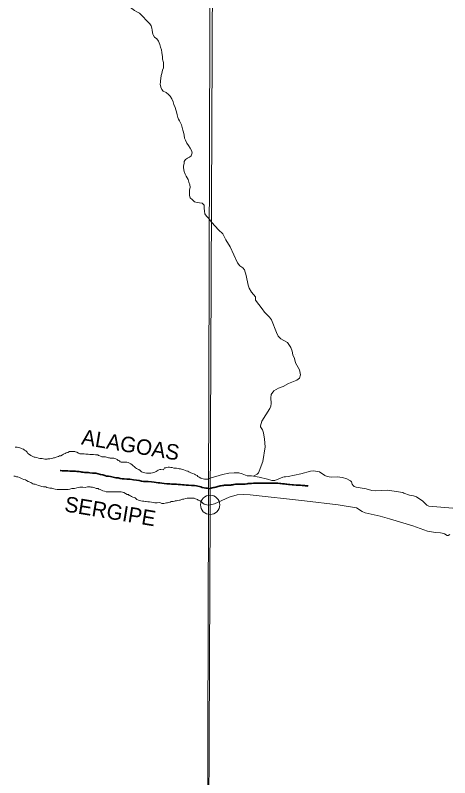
# Model space of a CAD drawing. Extents: x 553962 to 842807, y 8883888 to 9032388.
# Drawn here: x 595557 to 597811, y 8902976 to 8906931 of the extents above; entities that cross this region are included whole.
import ezdxf
from ezdxf.enums import TextEntityAlignment as Align

# ---------------------------------------------------------------- set-up
doc = ezdxf.new("R2010")
doc.units = 0
doc.header["$LTSCALE"] = 200
doc.header["$PDMODE"] = 32
doc.header["$PDSIZE"] = 100
doc.linetypes.add('LONG_DASH_SHORT_DASH', pattern=[9.9, 6, -1.2, 1.5, -1.2])
doc.layers.add('6', color=7, linetype='Continuous', lineweight=13)

msp = doc.modelspace()

# ---------------------------------------------------------------- linework, layer by layer
at = {"layer": '6'}
msp.add_line((597009.3, 8905170.6), (597009.5, 8905170.5), dxfattribs=at)
for points in [[(596655.5, 8924715.8), (596593.3, 8909930.3), (596531.7, 8896026.7)], [(596271.3, 8906832.7), (596268.8, 8906840.6), (596267.4, 8906852.6), (596266, 8906863.6), (596262.5, 8906875.6), (596254.5, 8906886.2), (596246.1, 8906895.2), (596235.1, 8906906.3), (596222.2, 8906920.4), (596211.2, 8906932.4), (596201.2, 8906941), (596187.3, 8906949.1), (596175.3, 8906955.7), (596161.8, 8906966.2), (596149.8, 8906973.8), (596139.9, 8906984.4), (596128.4, 8906996.9), (596121.5, 8907010), (596118, 8907020.5), (596117.5, 8907024.2)], [(596279.7, 8906817), (596272.3, 8906829.5), (596271.3, 8906832.7)], [(596461.2, 8906005.4), (596461.2, 8906022.7), (596463.8, 8906039.2), (596463.4, 8906051.2), (596457.4, 8906065.3), (596453.5, 8906078.3), (596444.6, 8906095.4), (596439.1, 8906106.9), (596433.7, 8906120.9), (596429.8, 8906138.5), (596429.8, 8906149), (596432.9, 8906162), (596433.9, 8906171.5), (596439.5, 8906182), (596451, 8906189.9), (596461, 8906195.4), (596470.1, 8906202.3), (596474.2, 8906216.8), (596471.2, 8906229.4), (596464.2, 8906241.4), (596455.8, 8906256), (596447.9, 8906268), (596439.9, 8906282.6), (596434.5, 8906292.6), (596433, 8906308.7), (596429.1, 8906323.7), (596426.2, 8906335.2), (596422.7, 8906348.8), (596419.3, 8906361.8), (596413.8, 8906373.3), (596408.8, 8906382.4), (596403.4, 8906390.9), (596399.9, 8906400.4), (596397, 8906413.4), (596393.6, 8906429), (596389.6, 8906440), (596386.2, 8906452.6), (596379.7, 8906468.6), (596376.3, 8906481.6), (596368.8, 8906497.2), (596361.4, 8906511.2), (596351.4, 8906519.3), (596340, 8906529.4), (596324, 8906537.5), (596317.3, 8906546.3), (596312.9, 8906557.6), (596309.7, 8906572.8), (596311, 8906582.9), (596310.7, 8906590.6), (596312.8, 8906603.1), (596313.4, 8906618.6), (596316.9, 8906629.1), (596321.5, 8906645.1), (596325.6, 8906657.6), (596326.1, 8906673.6), (596325.7, 8906686.1), (596321.8, 8906703.6), (596321.3, 8906715.7), (596317.4, 8906737.2), (596316.5, 8906750.7), (596310, 8906765.8), (596307.1, 8906779.8), (596300.2, 8906796.3), (596291.2, 8906807.9), (596279.7, 8906817)], [(596838.8, 8905408.9), (596804, 8905452.2), (596802.6, 8905456.8), (596803.3, 8905469.9), (596782.8, 8905493.9), (596770.6, 8905515.5), (596764.7, 8905530.2), (596754.3, 8905581.4), (596745.9, 8905609.6), (596737.4, 8905621.2), (596722.8, 8905631.7), (596710.6, 8905646), (596672.1, 8905729.1), (596650.2, 8905765.8), (596633.6, 8905797.4), (596611.2, 8905818.6), (596577.4, 8905855.5), (596559.7, 8905877.5), (596548.7, 8905888.6), (596540.2, 8905900.2), (596538.3, 8905914.2), (596537.9, 8905930.7), (596537.5, 8905945.2), (596527, 8905955.3), (596513.5, 8905957.9), (596500.5, 8905959.4), (596487, 8905962.5), (596476, 8905972.6), (596464.6, 8905983.1), (596461.1, 8905995.7), (596461.2, 8906005.4)], [(596792.7, 8904540.1), (596811.4, 8904551.1), (596818.4, 8904557.4), (596822.7, 8904565.5), (596841.5, 8904615.9), (596853.2, 8904691.8), (596850.7, 8904732.7), (596845.1, 8904764.5), (596839.3, 8904781), (596829.4, 8904796.5), (596828.9, 8904802.2), (596837.1, 8904824.7), (596877.1, 8904890.7), (596882.8, 8904903.4), (596885.5, 8904918), (596882.5, 8904946.3), (596884.2, 8904964.5), (596897.9, 8904982), (596922.6, 8904996.6), (596946.5, 8905006.2), (596975.3, 8905021.5), (597017.5, 8905037.8), (597031.8, 8905049.4), (597037, 8905065), (597032.3, 8905091.9), (597011.4, 8905127.4), (597004.9, 8905150.7), (596996.7, 8905170.4), (596994.1, 8905188.6), (596987.3, 8905208), (596969.8, 8905234), (596935.4, 8905253.2), (596921.5, 8905266.1), (596912.2, 8905285.1), (596886, 8905350.5), (596875.4, 8905364.7), (596850.4, 8905390), (596838.8, 8905408.9)], [(595556.5, 8904690.4), (595567.5, 8904689.9), (595575, 8904688.3), (595585.5, 8904685.2), (595593, 8904682.7), (595599.9, 8904679.7), (595605.9, 8904675.6), (595612.4, 8904672.1), (595619.8, 8904665.5), (595623.3, 8904658), (595631.8, 8904653.4), (595637.2, 8904647.4), (595645.7, 8904643.3), (595654.7, 8904639.7), (595659.7, 8904638.2), (595669.6, 8904637.1), (595677.6, 8904633.6), (595684.1, 8904631.5)], [(595684.1, 8904631.5), (595696.6, 8904631.9), (595710.6, 8904628.3), (595718.1, 8904629.3), (595722.1, 8904629.3), (595726.6, 8904629.7), (595733.1, 8904629.7), (595737.1, 8904630.2), (595744.1, 8904632.1), (595751.7, 8904633.1), (595756.2, 8904634.6), (595760.7, 8904636), (595765.2, 8904637), (595769.2, 8904639), (595774.7, 8904640.4), (595781.2, 8904642.4), (595786.8, 8904645.4), (595793.3, 8904646.3), (595802.8, 8904650.3), (595807.8, 8904653.7), (595816.9, 8904657.2), (595821.4, 8904660.7), (595830.4, 8904663.6), (595839, 8904668.1), (595845, 8904668), (595850, 8904668), (595858, 8904667.9), (595866, 8904667.4), (595870.5, 8904665.8), (595877.5, 8904664.8), (595884.9, 8904659.7), (595891.4, 8904656.2), (595899.4, 8904656.1), (595903.4, 8904656.1), (595910.9, 8904656.1), (595914.9, 8904656), (595922.9, 8904655), (595927.4, 8904654.4), (595934.9, 8904653.9), (595943.4, 8904652.3), (595951.4, 8904652.3), (595956.4, 8904652.3), (595963.4, 8904652.2), (595973.4, 8904651.6), (595980.4, 8904651.1), (595984.9, 8904650.6), (595989.4, 8904647.5), (595995.3, 8904646), (596002.3, 8904641.9), (596006.8, 8904639.9), (596012.8, 8904639.9), (596025.8, 8904639.8), (596041.3, 8904635.2), (596045.8, 8904634.6), (596050.3, 8904633.6), (596056.3, 8904633.1), (596063.8, 8904633), (596067.8, 8904633), (596074.3, 8904632.4), (596079.3, 8904630.4), (596086.2, 8904626.9), (596090.2, 8904622.3), (596097.2, 8904619.3), (596100.7, 8904614.2), (596107.2, 8904613.2), (596113.7, 8904613.2), (596120.7, 8904613.1), (596124.7, 8904613.1), (596128.7, 8904613.1), (596136.2, 8904613), (596142.2, 8904611), (596149.6, 8904608.4), (596156.1, 8904604.4), (596163.6, 8904599.3), (596168, 8904593.3), (596174.5, 8904590.2), (596180.5, 8904583.7), (596186.9, 8904580.1), (596193.4, 8904576.1), (596197.9, 8904574.1), (596204.4, 8904570), (596211.3, 8904563.4), (596217.3, 8904560.4), (596222.8, 8904558.9), (596229.8, 8904557.3), (596238.8, 8904556.3), (596245.3, 8904556.2), (596249.3, 8904556.2), (596255.8, 8904556.1), (596260.3, 8904556.6), (596268.3, 8904557.6), (596272.8, 8904559), (596280.8, 8904561), (596288.9, 8904564.4), (596292.9, 8904567.9), (596298.4, 8904570.9), (596307, 8904574.3), (596312, 8904575.3), (596327, 8904573.2), (596331.5, 8904582.7), (596337.5, 8904584.1)], [(596337.5, 8904584.1), (596341.6, 8904585.6), (596350.1, 8904586.6), (596357.6, 8904586.5), (596364.6, 8904586), (596371.1, 8904585.9), (596379.5, 8904581.9), (596386.5, 8904581.3), (596393.5, 8904581.3), (596401.5, 8904580.7), (596408, 8904579.2), (596414, 8904578.1), (596419, 8904576.6), (596427, 8904575.5), (596432, 8904572.5), (596440, 8904569.4), (596444.5, 8904567.9), (596452, 8904566.9), (596457.4, 8904563.3), (596468.4, 8904558.2), (596478.9, 8904554.7), (596487.3, 8904550.1), (596492.3, 8904546.6), (596500.3, 8904543), (596504.3, 8904539), (596511.7, 8904535.4), (596519.2, 8904529.4), (596523.7, 8904527.8), (596531.7, 8904525.8), (596538.2, 8904524.7), (596545.2, 8904524.7), (596549.2, 8904524.7), (596554.2, 8904525.1), (596558.2, 8904525.1), (596568.1, 8904529.4), (596633, 8904549.7), (596665.5, 8904556.5), (596692.3, 8904558.4), (596717.2, 8904557), (596733.8, 8904552.4)], [(596822.7, 8904565.5), (596818.4, 8904557.4), (596811.4, 8904551.1), (596792.7, 8904540.1)], [(596823.3, 8904534.6), (596822.9, 8904534.3), (596866.1, 8904524.6), (596887.5, 8904518.1), (596904.4, 8904518.5), (596944.7, 8904535.2), (596952.2, 8904537.4), (596959.2, 8904537.7), (596972.2, 8904538.7), (597038.5, 8904552.3), (597088.9, 8904566.9), (597103.5, 8904567.8), (597135.1, 8904562.2), (597163.3, 8904544.4), (597175.5, 8904538.6), (597195.2, 8904535.8), (597227.3, 8904537.4), (597253.9, 8904534.1), (597277.1, 8904527.3), (597291.9, 8904517.4), (597296.9, 8904516.7), (597300.6, 8904511.3), (597305.1, 8904499.1), (597310, 8904491.8), (597315.9, 8904486.6), (597325.4, 8904483.2), (597377.2, 8904474.8), (597406.8, 8904466.6), (597425.4, 8904464.6), (597488, 8904467), (597567.9, 8904454.9)], [(596113, 8904457.9), (596106, 8904458.5), (596097.5, 8904459.1), (596092.5, 8904459.1), (596084.5, 8904459.1), (596079.5, 8904459.2), (596067.5, 8904459.2), (596057, 8904459.3), (596050, 8904459.4), (596042, 8904459.4), (596036.5, 8904459.5), (596028, 8904459.5), (596020, 8904462.6), (596012, 8904463.6), (596005, 8904467.7), (595998.5, 8904470.7), (595991.5, 8904472.8), (595987.1, 8904475.8), (595977.6, 8904476.9), (595969.6, 8904479.9), (595965.1, 8904481.5), (595958.6, 8904482.5), (595950.1, 8904484.1), (595945.1, 8904485.1), (595936.6, 8904485.2), (595932.1, 8904485.2), (595920.1, 8904482.3), (595908.6, 8904483.3), (595897.6, 8904483.4), (595892.1, 8904482.9), (595885.1, 8904482), (595877, 8904480.5), (595865, 8904477.1), (595851, 8904476.2), (595840.5, 8904473.3), (595832.5, 8904471.8), (595827, 8904470.9), (595816.4, 8904470.4), (595808.4, 8904470.5), (595798.4, 8904470.5), (595789.4, 8904470.6), (595783.9, 8904470.6), (595773.9, 8904470.7), (595763.9, 8904472.3), (595756.9, 8904473.8), (595747, 8904477.4), (595737, 8904478), (595730.5, 8904479.5), (595721, 8904481.1), (595715.5, 8904484.6), (595704.5, 8904485.7), (595695, 8904487.2), (595684.5, 8904490.3), (595678, 8904491.9), (595669.1, 8904494.9), (595661.1, 8904498), (595653.6, 8904499), (595649.1, 8904500.6), (595642.6, 8904503.6), (595637.6, 8904507.2), (595628.7, 8904510.2), (595623.7, 8904513.3), (595615.2, 8904518.3), (595609.7, 8904521.9), (595601.8, 8904522.9), (595593.3, 8904527), (595585.8, 8904529.5), (595579.3, 8904533.6), (595571.3, 8904536.1), (595563.8, 8904537.7), (595557.3, 8904539.7), (595550.4, 8904540.8)], [(596733.8, 8904552.4), (596760.4, 8904542.1), (596781.9, 8904541.7), (596822.9, 8904534.3)], [(596137.9, 8904445.3), (596128.4, 8904450.8), (596120.5, 8904454.9), (596113, 8904457.9)], [(596412.8, 8904415.9), (596408.8, 8904415.9), (596401.3, 8904414.5), (596394.3, 8904413), (596387.2, 8904411.6), (596383.2, 8904410.6), (596376.2, 8904409.6), (596366.7, 8904408.2), (596360.2, 8904405.2), (596351.2, 8904404.3), (596347.2, 8904402.8), (596341.2, 8904401.9), (596335.1, 8904399.9), (596328.6, 8904398.9), (596324.1, 8904398.5), (596317.1, 8904398.5), (596307.2, 8904403.6), (596293.1, 8904401.2), (596281.1, 8904402.3), (596273.1, 8904403.8), (596264.6, 8904405.4), (596253.7, 8904406.4), (596244.7, 8904407.5), (596236.7, 8904408.1), (596232.2, 8904409.1), (596224.2, 8904410.2), (596216.7, 8904411.2), (596208.7, 8904412.8), (596201.2, 8904414.3), (596196.2, 8904415.8), (596188.7, 8904418.9), (596184.2, 8904422.9), (596179.3, 8904428), (596173.3, 8904429), (596167.8, 8904432.1), (596160.3, 8904435.1), (596155.8, 8904438.6), (596148.8, 8904439.7), (596144.9, 8904444.7), (596137.9, 8904445.3)], [(597784.5, 8904240.9), (597780.8, 8904243.5), (597763, 8904246.9), (597737.7, 8904248), (597696.4, 8904255.7), (597619.9, 8904282.1), (597498.2, 8904319.6), (597450, 8904332.9), (597372.6, 8904350.3), (597356, 8904357.7), (597326.5, 8904376.3), (597232.9, 8904391.8), (597058.1, 8904411.6), (596775.1, 8904444.1), (596742.4, 8904446), (596707.5, 8904442.8), (596667.4, 8904431.6), (596590.1, 8904397.6), (596568.1, 8904391.5), (596558.7, 8904389.9), (596551.2, 8904391.5), (596544.2, 8904394), (596537.7, 8904395.6), (596530.7, 8904401.1), (596526.2, 8904404.6), (596520.3, 8904409.2), (596515.8, 8904412.2), (596506.8, 8904415.8), (596502.3, 8904419.3), (596492.4, 8904422.4), (596485.4, 8904425.4), (596475.9, 8904426), (596467.4, 8904426.1), (596458.4, 8904426.1), (596449.4, 8904426.2), (596440.4, 8904425.2), (596431.8, 8904421.3), (596424.8, 8904421.3), (596420.3, 8904419.9), (596412.8, 8904415.9)], [(597567.9, 8904454.9), (597572.2, 8904452.6), (597602.6, 8904441.6), (597622.9, 8904438.2), (597638, 8904432.9), (597672.2, 8904410.2), (597691.4, 8904390.6), (597701.7, 8904384.3), (597826.9, 8904374.3)], [(597812.2, 8904237.9), (597802.9, 8904232.5), (597797.6, 8904231.9), (597784.5, 8904240.9)]]:
    msp.add_lwpolyline(points, dxfattribs=at)
msp.add_lwpolyline([(596575.8, 8909932.4), (585614.8, 8909969.8), (585583.8, 8898914.4), (596544.8, 8898874.9)], close=True, dxfattribs=at)
at = {"layer": '6', "linetype": 'LONG_DASH_SHORT_DASH', "lineweight": 35}
for points in [[(596403.1, 8904497.6), (596393.1, 8904498.1), (596385.2, 8904498.7), (596380.2, 8904498.7), (596375.2, 8904499.2), (596367.2, 8904499.3), (596358.7, 8904499.8), (596344.2, 8904500.9), (596330.2, 8904502), (596318.2, 8904504.5), (596307.2, 8904505.1), (596298.2, 8904506.1), (596288.7, 8904507.2), (596278.2, 8904509.8), (596264.2, 8904510.3), (596247.2, 8904512.9), (596234.7, 8904513), (596223.2, 8904513.5), (596212.2, 8904514.6), (596200.3, 8904518.2), (596185.3, 8904519.2), (596169.8, 8904521.8), (596151.3, 8904524.9), (596136.3, 8904525), (596122.8, 8904526.1), (596111.8, 8904527.1), (596101.3, 8904528.2), (596090.4, 8904531.3), (596079.4, 8904531.8), (596065.9, 8904534.4), (596051.9, 8904538), (596040.4, 8904540.5), (596030.9, 8904541.1), (596021.4, 8904543.6), (596012, 8904546.7), (596000, 8904549.8), (595987, 8904552.8), (595974.5, 8904555.4), (595957.5, 8904556), (595944.5, 8904557.1), (595937.6, 8904559.6), (595929.5, 8904559.6), (595924, 8904559.7), (595915.6, 8904560.2), (595909.6, 8904560.7), (595903.1, 8904561.8), (595897.1, 8904562.3), (595889.1, 8904563.9), (595883.1, 8904564.4), (595877.1, 8904564.9), (595870.1, 8904566), (595860.6, 8904566), (595850.1, 8904566.6), (595840.6, 8904567.1), (595830.1, 8904567.2), (595819.1, 8904567.2), (595811.1, 8904567.8), (595805.6, 8904567.8), (595800.1, 8904568.8), (595791.6, 8904569.4), (595790.2, 8904569.7)], [(596573, 8904478.7), (596564, 8904475.2), (596553, 8904478.3), (596546, 8904478.8), (596537, 8904479.3), (596527, 8904481.9), (596519.6, 8904484.9), (596512.1, 8904486), (596504.6, 8904488.5), (596497.1, 8904489.6), (596487.6, 8904492.1), (596479.1, 8904492.2), (596471.6, 8904492.7), (596456.6, 8904493.3), (596443.6, 8904493.9), (596434.1, 8904494.9), (596425.1, 8904495.5), (596414.6, 8904496.5), (596403.1, 8904497.6)], [(597057.4, 8904492), (597045.7, 8904492.5), (597036, 8904494), (597030.4, 8904494), (597021.8, 8904494.5), (597014.2, 8904494.5), (597000.4, 8904495.6), (596993.3, 8904496.1), (596981.1, 8904496.6), (596975, 8904497.6), (596965.8, 8904498.1), (596961.2, 8904498.1), (596954.1, 8904499.7), (596950, 8904500.2), (596942.9, 8904500.7), (596935.3, 8904501.7), (596929.7, 8904502.7), (596920, 8904503.7), (596907.3, 8904503.7), (596895.6, 8904503.7), (596890, 8904503.7), (596880.3, 8904503.7), (596874.2, 8904503.7), (596857.9, 8904503.7), (596850.8, 8904503.7), (596839.1, 8904503.7), (596833, 8904503.7), (596821.8, 8904503.7), (596815.7, 8904503.7), (596801.4, 8904503.7), (596793.8, 8904503.7), (596782.1, 8904502.7), (596776, 8904502.2), (596765.8, 8904501.7), (596760.7, 8904500.7), (596750.6, 8904499.6), (596741.9, 8904499.6), (596737.3, 8904499.6), (596728.7, 8904499.6), (596720.5, 8904498.6), (596710.8, 8904498.6), (596699.7, 8904498.1), (596691, 8904496.6), (596686.4, 8904496.1), (596679.3, 8904495.6), (596675.2, 8904494.5), (596665.6, 8904494), (596659.5, 8904494), (596654.4, 8904494), (596648.8, 8904494), (596642.7, 8904494), (596637.1, 8904492.5), (596633, 8904492.5), (596625.9, 8904490.4), (596620.3, 8904489.4), (596614.7, 8904487.9), (596608.6, 8904486.3), (596603.5, 8904484.8), (596597.4, 8904483.8), (596591.3, 8904482.3), (596585.2, 8904480.7), (596579.1, 8904479.7), (596573, 8904478.7), (596573, 8904478.7), (596573, 8904478.7)], [(597076.6, 8904488.8), (597073.7, 8904489.4), (597063, 8904490.4), (597057.4, 8904492)]]:
    msp.add_lwpolyline(points, dxfattribs=at)
at = {"layer": '6'}
msp.add_point((596568.1, 8904391.5), dxfattribs=at)

# ---------------------------------------------------------------- texts
for s, p in [('ALAGOAS', (596148.9, 8904663.4)), ('SERGIPE', (596043.6, 8904319))]:
    msp.add_text(s, height=80, rotation=350.533, dxfattribs=at).set_placement(p, align=Align.CENTER)

doc.saveas('drawing.dxf')
